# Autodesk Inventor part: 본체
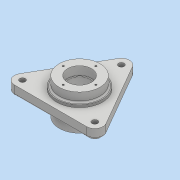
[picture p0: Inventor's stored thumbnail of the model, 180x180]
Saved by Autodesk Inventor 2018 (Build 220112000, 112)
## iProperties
Created: 2023-04
Part Number: 본체
Material: 일반
Document SubType Name: Modeling
Designer: 강의실04
Density: 1 g/cm^3
Appearance: 기본값
Author: 강의실04
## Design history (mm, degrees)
sketch "스케치1"
  geometry: L1 (-13.856, 90)-(-84.87, -33); L2 (-71.014, -57)-(71.014, -57); L3 (84.87, -33)-(13.856, 90); A1 r 16 centre (0, 82) between (13.856, 90) and (-13.856, 90); A2 r 16 centre (-71.014, -41) between (-84.87, -33) and (-71.014, -57); A3 r 16 centre (71.014, -41) between (71.014, -57) and (84.87, -33); 2 further points
  constraints: 6 end point, 6 point on circle, 6 tangent, 3 centre point, 2 equal radius, 1 coincident, 1 horizontal
  dimensions: "d11" = 60 deg angle of L3 L1; "d12" = 60 deg angle of L2 L1; "d13" = 16 radius of A1 (derived)
extrude "돌출1" new body sketch "스케치1" distance "d14" = 18; taper "d15" = 0 deg
sketch "스케치3"
  geometry: C1 r 45 at (0, 0); C2 r 40 at (0, 0); 1 further point
  constraints: 2 centre point, 2 coincident
  dimensions: "d22" = 90 diameter of C1; "d23" = 80 diameter of C2
extrude "돌출3" join sketch "스케치3" distance "d24" = 5; taper "d25" = 0 deg
sketch "스케치4"
  geometry: L1 (13.856, 90)-(84.87, -33) reference; L2 (71.014, -57)-(-71.014, -57) reference; L3 (-84.87, -33)-(-13.856, 90) reference; C1 r 40 at (0, 0) reference; C2 r 45 at (0, 0) reference; A1 r 16 centre (0, 82) between (13.856, 90) and (-13.856, 90) reference; A2 r 16 centre (71.014, -41) between (71.014, -57) and (84.87, -33) reference; A3 r 16 centre (-71.014, -41) between (-84.87, -33) and (-71.014, -57) reference; 1 further point
extrude "돌출4" join sketch "스케치4" distance "d26" = 23; taper "d27" = 0 deg
sketch "스케치5"
  geometry: C1 r 40 at (0, 0); 1 further point
  constraints: 1 centre point, 1 coincident
  dimensions: "d28" = 80 diameter of C1
extrude "돌출5" join sketch "스케치5" distance "d29" = 29; taper "d30" = 0 deg
hole "구멍1" diameter "d33" = 42; stored, may be unused: countersink angle "d37" = 90 deg, drill point angle "d39" = 118 deg; dims "d31" = 10, "d32" = 10, "d34" = 6, "d35" = 47, "d36" = 17, "d38" = 8
hole "구멍2" diameter "d42" = 42; stored, may be unused: countersink angle "d46" = 90 deg, drill point angle "d48" = 118 deg; dims "d40" = 10, "d41" = 10, "d43" = 6, "d44" = 47, "d45" = 17, "d47" = 8
sketch "스케치6"
  geometry: L1 (13.856, 90)-(84.87, -33) reference; L2 (71.014, -57)-(-71.014, -57) reference; L3 (-84.87, -33)-(-13.856, 90) reference; C1 r 21 at (0, 0) reference; C2 r 40 at (0, 0) reference; C3 r 11 at (0, 82); C4 r 11 at (-71.014, -41); C5 r 11 at (71.014, -41); A1 r 16 centre (0, 82) between (13.856, 90) and (-13.856, 90) reference; A2 r 16 centre (71.014, -41) between (71.014, -57) and (84.87, -33) reference; A3 r 16 centre (-71.014, -41) between (-84.87, -33) and (-71.014, -57) reference; 1 further point
  constraints: 3 centre point, 2 coincident
  dimensions: "d49" = 22 diameter of C3; "d50" = 22 diameter of C4; "d51" = 22 diameter of C5
  node "절단 모서리 투영3"
sketch "스케치7"
  geometry: L1 (13.856, 90)-(84.87, -33) reference; L2 (71.014, -57)-(-71.014, -57) reference; L3 (-84.87, -33)-(-13.856, 90) reference; C1 r 21 at (0, 0) reference; C2 r 45 at (0, 0) reference; A1 r 16 centre (0, 82) between (13.856, 90) and (-13.856, 90) reference; A2 r 16 centre (71.014, -41) between (71.014, -57) and (84.87, -33) reference; A3 r 16 centre (-71.014, -41) between (-84.87, -33) and (-71.014, -57) reference; 1 further point
hole "구멍3" sketch "스케치7" at (0, 82), (-71.014, -41), (71.014, -41) diameter "d54" = 11; stored, may be unused: countersink angle "d58" = 90 deg, drill point angle "d60" = 118 deg; dims "d55" = 6, "d56" = 47, "d57" = 17, "d59" = 8
fillet "모깎기2" dims "d62" = 3
fillet "모깎기3" dims "d63" = 3
sketch "스케치8" dims "d65" = 64
  geometry: C1 r 40 at (0, 0) reference; C2 r 23.5 at (0, 0) reference; 3 further points
  constraints: 1 coincident, 1 vertical alignment, 2 other
hole "구멍4" sketch "스케치8" at (0, 32) diameter "d66" = 3.459; stored, may be unused: countersink angle "d70" = 90 deg, drill point angle "d72" = 118 deg; dims "d67" = 8, "d68" = 47, "d69" = 17, "d71" = 10
node "작업 평면1"
sketch "스케치9"
  geometry: L1 (13.856, 90)-(84.87, -33) reference; L2 (71.014, -57)-(-71.014, -57) reference; L3 (-84.87, -33)-(-13.856, 90) reference; C1 r 43 at (0, 0) reference; C2 r 5.5 at (71.014, -41) reference; C3 r 5.5 at (0, 82) reference; C4 r 5.5 at (-71.014, -41) reference; C5 r 21 at (0, 0) reference; A1 r 16 centre (0, 82) between (13.856, 90) and (-13.856, 90) reference; A2 r 16 centre (71.014, -41) between (71.014, -57) and (84.87, -33) reference; A3 r 16 centre (-71.014, -41) between (-84.87, -33) and (-71.014, -57) reference; 1 further point
  node "절단 모서리 투영6"
extrude "돌출7" join sketch "스케치6" distance "d76" = 3; taper "d77" = 0 deg
sketch "스케치10"
  geometry: L1 (13.856, 90)-(84.87, -33) reference; L2 (71.014, -57)-(-71.014, -57) reference; L3 (-84.87, -33)-(-13.856, 90) reference; C1 r 11 at (-71.014, -41) reference; C2 r 11 at (0, 82) reference; C3 r 11 at (71.014, -41) reference; C4 r 43 at (0, 0) reference; C5 r 5.5 at (71.014, -41) reference; C6 r 5.5 at (0, 82) reference; C7 r 5.5 at (-71.014, -41) reference; C8 r 21 at (0, 0) reference; C9 r 5.5 at (0, 82); C10 r 5.5 at (-71.014, -41); C11 r 5.5 at (71.014, -41); A1 r 16 centre (0, 82) between (13.856, 90) and (-13.856, 90) reference; A2 r 16 centre (71.014, -41) between (71.014, -57) and (84.87, -33) reference; A3 r 16 centre (-71.014, -41) between (-84.87, -33) and (-71.014, -57) reference; 1 further point
  constraints: 3 centre point, 2 coincident
  dimensions: "d78" = 11 diameter of C9; "d79" = 11 diameter of C10; "d80" = 11 diameter of C11
extrude "돌출8" cut sketch "스케치10" distance "d81" = 5; taper "d82" = 0 deg
fillet "모깎기5" dims "d83" = 0.6
sketch "스케치11"
  geometry: 2 further points
  constraints: 1 other
  dimensions: "d84" = 60 vertical distance of point (0, 0) point (0.303, 60)
feature "엠보싱1" sketch "스케치11" dims "d11" = 60 deg, "d12" = 60 deg, "d13" = 16 (derived), "d85" = 0.5, "d86" = 0
fillet "모깎기8" dims "d89" = 3
fillet "모깎기9" dims "d90" = 3
node "솔리드1"
pattern_circular "원형 패턴1" dims angle "d74" = 360 deg
mirror "미러1"
node "절단 모서리 투영2"
node "절단 모서리 투영4"
node "절단 모서리 투영5"
node "절단 모서리 투영7"
